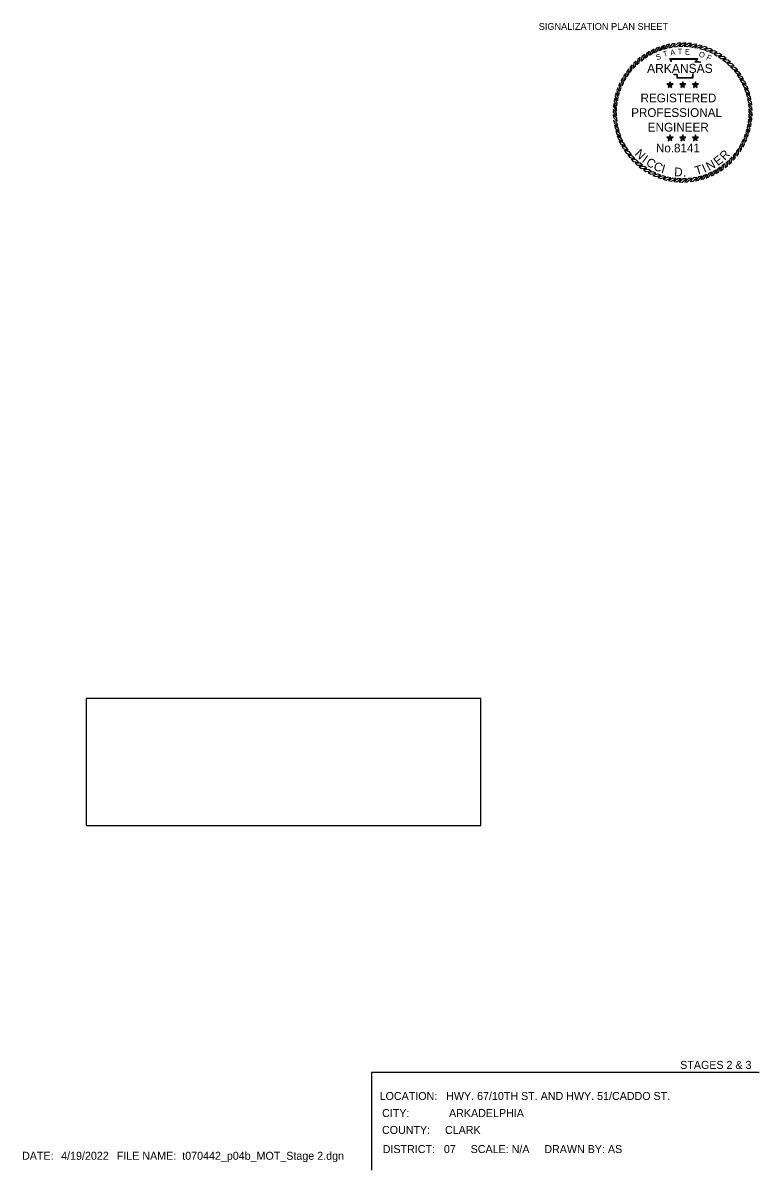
# Model space of a CAD drawing. Extents: x 418532 to 419834, y -565899 to -565282.
# Drawn here: x 419448 to 419834, y -565899 to -565297 of the extents above; entities that cross this region are included whole.
import ezdxf

# ---------------------------------------------------------------- set-up
doc = ezdxf.new("R2010")
doc.units = 0
for name, color, linetype in [('G-ANNO-SYMB', 7, 'Continuous'), ('G-ANNO-TEXT', 7, 'Continuous'), ('Level 10', 7, 'Continuous'), ('Level 57', 7, 'Continuous'), ('V-SIGNAL-LOOP', 7, 'Continuous')]:
    doc.layers.add(name, color=color, linetype=linetype)

msp = doc.modelspace()

# ---------------------------------------------------------------- linework, layer by layer
at = {"layer": 'G-ANNO-SYMB'}
for points in [[(419790.16, -565307.34), (419788.61, -565307.54), (419786.7, -565309.59), (419788.37, -565309.27)], [(419793.02, -565307.15), (419791.46, -565307.23), (419789.39, -565309.11), (419791.08, -565308.93)], [(419795.89, -565307.18), (419794.32, -565307.13), (419792.12, -565308.85), (419793.81, -565308.8)], [(419798.74, -565307.43), (419797.18, -565307.26), (419794.85, -565308.81), (419796.54, -565308.89)], [(419774.13, -565313.06), (419772.83, -565313.95), (419772.06, -565316.64), (419773.4, -565315.6)], [(419776.58, -565311.59), (419775.22, -565312.37), (419774.24, -565314.99), (419775.66, -565314.06)], [(419779.15, -565310.32), (419777.73, -565310.99), (419776.55, -565313.53), (419778.04, -565312.71)], [(419781.81, -565309.25), (419780.34, -565309.81), (419778.96, -565312.25), (419780.51, -565311.55)], [(419784.54, -565308.4), (419783.03, -565308.84), (419781.47, -565311.16), (419783.07, -565310.58)], [(419787.33, -565307.76), (419785.8, -565308.08), (419784.06, -565310.27), (419785.69, -565309.82)], [(419801.56, -565307.91), (419800.02, -565307.62), (419797.58, -565308.98), (419799.26, -565309.19)], [(419804.34, -565308.61), (419802.83, -565308.2), (419800.28, -565309.36), (419801.94, -565309.7)], [(419807.05, -565309.52), (419805.58, -565309), (419802.95, -565309.95), (419804.58, -565310.42)], [(419809.69, -565310.65), (419808.26, -565310.01), (419805.56, -565310.75), (419807.15, -565311.35)], [(419812.23, -565311.97), (419810.85, -565311.22), (419808.11, -565311.76), (419809.64, -565312.48)], [(419814.65, -565313.5), (419813.34, -565312.64), (419810.56, -565312.96), (419812.03, -565313.8)], [(419767.55, -565318.56), (419766.49, -565319.73), (419766.37, -565322.52), (419767.43, -565321.2)], [(419769.59, -565316.56), (419768.45, -565317.64), (419768.11, -565320.41), (419769.27, -565319.18)], [(419771.79, -565314.72), (419770.57, -565315.71), (419770.01, -565318.45), (419771.27, -565317.31)], [(419816.95, -565315.21), (419815.71, -565314.25), (419812.92, -565314.35), (419814.32, -565315.3)], [(419819.11, -565317.09), (419817.95, -565316.04), (419815.15, -565315.91), (419816.48, -565316.97)], [(419821.11, -565319.14), (419820.04, -565317.99), (419817.26, -565317.65), (419818.5, -565318.81)], [(419822.95, -565321.33), (419821.96, -565320.11), (419819.23, -565319.55), (419820.37, -565320.81)], [(419762.43, -565325.45), (419761.68, -565326.82), (419762.21, -565329.57), (419762.94, -565328.03)], [(419763.96, -565323.02), (419763.1, -565324.33), (419763.41, -565327.11), (419764.25, -565325.64)], [(419765.66, -565320.72), (419764.71, -565321.96), (419764.8, -565324.76), (419765.76, -565323.35)], [(419824.61, -565323.67), (419823.72, -565322.37), (419821.03, -565321.6), (419822.07, -565322.94)], [(419826.08, -565326.13), (419825.3, -565324.77), (419822.68, -565323.79), (419823.61, -565325.2)], [(419759.98, -565330.62), (419759.45, -565332.09), (419760.41, -565334.72), (419760.88, -565333.09)], [(419761.11, -565327.98), (419760.46, -565329.41), (419761.21, -565332.11), (419761.81, -565330.52)], [(419787.4, -565329.08), (419787.02, -565328.57), (419785.81, -565328.57), (419786.79, -565329.28)], [(419787.4, -565329.08), (419786.79, -565329.28), (419786.42, -565330.43), (419787.4, -565329.72)], [(419787.4, -565329.08), (419787.77, -565328.57), (419787.4, -565327.41), (419787.02, -565328.57)], [(419787.4, -565329.08), (419788, -565329.28), (419788.98, -565328.57), (419787.77, -565328.57)], [(419787.4, -565329.08), (419787.4, -565329.72), (419788.38, -565330.43), (419788, -565329.28)], [(419794.06, -565329.08), (419793.69, -565328.57), (419792.48, -565328.57), (419793.46, -565329.28)], [(419794.06, -565329.08), (419793.46, -565329.28), (419793.08, -565330.43), (419794.06, -565329.72)], [(419794.06, -565329.08), (419794.44, -565328.57), (419794.06, -565327.41), (419793.69, -565328.57)], [(419794.06, -565329.08), (419794.67, -565329.28), (419795.65, -565328.57), (419794.44, -565328.57)], [(419794.06, -565329.08), (419794.06, -565329.72), (419795.04, -565330.43), (419794.67, -565329.28)], [(419800.73, -565329.08), (419800.36, -565328.57), (419799.15, -565328.57), (419800.13, -565329.28)], [(419800.73, -565329.08), (419800.13, -565329.28), (419799.75, -565330.43), (419800.73, -565329.72)], [(419800.73, -565329.08), (419801.11, -565328.57), (419800.73, -565327.41), (419800.36, -565328.57)], [(419800.73, -565329.08), (419801.34, -565329.28), (419802.32, -565328.57), (419801.11, -565328.57)], [(419800.73, -565329.08), (419800.73, -565329.72), (419801.71, -565330.43), (419801.34, -565329.28)], [(419827.35, -565328.69), (419826.68, -565327.27), (419824.15, -565326.09), (419824.96, -565327.58)], [(419828.42, -565331.35), (419827.86, -565329.88), (419825.43, -565328.51), (419826.12, -565330.05)], [(419829.27, -565334.08), (419828.83, -565332.58), (419826.51, -565331.01), (419827.09, -565332.61)], [(419758.37, -565336.11), (419758.08, -565337.65), (419759.43, -565340.1), (419759.65, -565338.41)], [(419759.07, -565333.33), (419758.66, -565334.85), (419759.82, -565337.39), (419760.16, -565335.73)], [(419829.91, -565336.87), (419829.59, -565335.34), (419827.4, -565333.6), (419827.85, -565335.23)], [(419830.33, -565339.71), (419830.13, -565338.15), (419828.09, -565336.24), (419828.4, -565337.91)], [(419757.64, -565341.79), (419757.59, -565343.35), (419759.31, -565345.56), (419759.26, -565343.86)], [(419757.89, -565338.93), (419757.72, -565340.49), (419759.27, -565342.82), (419759.35, -565341.13)], [(419830.53, -565342.56), (419830.45, -565341), (419828.56, -565338.94), (419828.74, -565340.62)], [(419830.49, -565345.43), (419830.54, -565343.86), (419828.82, -565341.66), (419828.87, -565343.35)], [(419757.6, -565344.65), (419757.68, -565346.22), (419759.57, -565348.28), (419759.39, -565346.59)], [(419757.8, -565347.51), (419758, -565349.06), (419760.04, -565350.97), (419759.73, -565349.3)], [(419829.76, -565351.1), (419830.05, -565349.56), (419828.7, -565347.12), (419828.48, -565348.8)], [(419830.24, -565348.28), (419830.41, -565346.72), (419828.86, -565344.39), (419828.78, -565346.08)], [(419758.22, -565350.34), (419758.54, -565351.88), (419760.73, -565353.62), (419760.28, -565351.98)], [(419758.86, -565353.13), (419759.3, -565354.64), (419761.62, -565356.2), (419761.04, -565354.61)], [(419787.4, -565357.01), (419787.77, -565356.5), (419787.4, -565355.34), (419787.02, -565356.5)], [(419794.06, -565357.01), (419794.44, -565356.5), (419794.06, -565355.34), (419793.69, -565356.5)], [(419800.73, -565357.01), (419801.11, -565356.5), (419800.73, -565355.34), (419800.36, -565356.5)], [(419827.02, -565359.23), (419827.67, -565357.8), (419826.92, -565355.11), (419826.32, -565356.69)], [(419828.15, -565356.6), (419828.68, -565355.12), (419827.72, -565352.49), (419827.25, -565354.12)], [(419829.06, -565353.88), (419829.47, -565352.37), (419828.31, -565349.82), (419827.97, -565351.48)], [(419759.71, -565355.87), (419760.27, -565357.33), (419762.7, -565358.71), (419762.01, -565357.16)], [(419760.78, -565358.52), (419761.45, -565359.94), (419763.98, -565361.12), (419763.17, -565359.64)], [(419762.05, -565361.09), (419762.83, -565362.45), (419765.45, -565363.43), (419764.52, -565362.01)], [(419787.4, -565357.01), (419787.02, -565356.5), (419785.81, -565356.5), (419786.79, -565357.21)], [(419787.4, -565357.01), (419786.79, -565357.21), (419786.42, -565358.36), (419787.4, -565357.65)], [(419787.4, -565357.01), (419788, -565357.21), (419788.98, -565356.5), (419787.77, -565356.5)], [(419787.4, -565357.01), (419787.4, -565357.65), (419788.38, -565358.36), (419788, -565357.21)], [(419794.06, -565357.01), (419793.69, -565356.5), (419792.48, -565356.5), (419793.46, -565357.21)], [(419794.06, -565357.01), (419793.46, -565357.21), (419793.08, -565358.36), (419794.06, -565357.65)], [(419794.06, -565357.01), (419794.67, -565357.21), (419795.65, -565356.5), (419794.44, -565356.5)], [(419794.06, -565357.01), (419794.06, -565357.65), (419795.04, -565358.36), (419794.67, -565357.21)], [(419800.73, -565357.01), (419800.36, -565356.5), (419799.15, -565356.5), (419800.13, -565357.21)], [(419800.73, -565357.01), (419800.13, -565357.21), (419799.75, -565358.36), (419800.73, -565357.65)], [(419800.73, -565357.01), (419801.34, -565357.21), (419802.32, -565356.5), (419801.11, -565356.5)], [(419800.73, -565357.01), (419800.73, -565357.65), (419801.71, -565358.36), (419801.34, -565357.21)], [(419824.17, -565364.19), (419825.03, -565362.88), (419824.72, -565360.1), (419823.88, -565361.58)], [(419825.7, -565361.77), (419826.45, -565360.39), (419825.92, -565357.65), (419825.19, -565359.18)], [(419763.52, -565363.55), (419764.41, -565364.84), (419767.09, -565365.61), (419766.06, -565364.27)], [(419765.18, -565365.88), (419766.16, -565367.1), (419768.9, -565367.66), (419767.76, -565366.41)], [(419818.54, -565370.65), (419819.68, -565369.58), (419820.02, -565366.8), (419818.86, -565368.04)], [(419820.58, -565368.65), (419821.64, -565367.49), (419821.76, -565364.69), (419820.7, -565366.02)], [(419822.47, -565366.49), (419823.42, -565365.25), (419823.33, -565362.46), (419822.37, -565363.86)], [(419767.02, -565368.08), (419768.09, -565369.22), (419770.87, -565369.56), (419769.63, -565368.4)], [(419769.02, -565370.13), (419770.18, -565371.18), (419772.98, -565371.3), (419771.65, -565370.24)], [(419771.18, -565372.01), (419772.42, -565372.97), (419775.21, -565372.87), (419773.81, -565371.92)], [(419773.48, -565373.72), (419774.79, -565374.57), (419777.57, -565374.26), (419776.1, -565373.42)], [(419808.98, -565376.89), (419810.4, -565376.22), (419811.58, -565373.69), (419810.09, -565374.5)], [(419811.55, -565375.62), (419812.91, -565374.84), (419813.89, -565372.22), (419812.47, -565373.15)], [(419814, -565374.15), (419815.3, -565373.26), (419816.07, -565370.58), (419814.73, -565371.62)], [(419816.34, -565372.49), (419817.56, -565371.51), (419818.12, -565368.77), (419816.86, -565369.91)], [(419775.9, -565375.24), (419777.28, -565375.99), (419780.02, -565375.46), (419778.49, -565374.74)], [(419778.44, -565376.57), (419779.87, -565377.21), (419782.57, -565376.46), (419780.98, -565375.86)], [(419781.08, -565377.69), (419782.55, -565378.22), (419785.18, -565377.26), (419783.55, -565376.79)], [(419783.79, -565378.6), (419785.3, -565379.01), (419787.85, -565377.85), (419786.19, -565377.51)], [(419786.57, -565379.3), (419788.11, -565379.59), (419790.55, -565378.24), (419788.87, -565378.03)], [(419789.39, -565379.78), (419790.95, -565379.95), (419793.28, -565378.41), (419791.59, -565378.33)], [(419792.24, -565380.04), (419793.81, -565380.08), (419796.01, -565378.36), (419794.32, -565378.41)], [(419795.11, -565380.07), (419796.67, -565379.99), (419798.74, -565378.1), (419797.05, -565378.29)], [(419797.96, -565379.87), (419799.52, -565379.67), (419801.43, -565377.63), (419799.76, -565377.95)], [(419800.8, -565379.46), (419802.33, -565379.13), (419804.07, -565376.94), (419802.44, -565377.39)], [(419803.59, -565378.82), (419805.1, -565378.37), (419806.66, -565376.06), (419805.06, -565376.63)], [(419806.32, -565377.96), (419807.79, -565377.4), (419809.17, -565374.97), (419807.62, -565375.67)]]:
    msp.add_lwpolyline(points, close=True, dxfattribs=at)
for points in [[(419788.22, -565317.13), (419787.37, -565315.29), (419802.08, -565315.28), (419800.85, -565316.83), (419801.85, -565316.82), (419802.69, -565316.8), (419803.52, -565316.9)], [(419788.43, -565317.04), (419787.74, -565315.53), (419801.6, -565315.52), (419800.37, -565317.07), (419801.86, -565317.05), (419802.68, -565317.04), (419803.5, -565317.13)], [(419799.76, -565323.3), (419799.51, -565323.5), (419799.43, -565323.81), (419799.35, -565324.57), (419799.35, -565325.59), (419791.13, -565325.59), (419791.13, -565324.22), (419791.13, -565323.91), (419790.8, -565323.81), (419789.63, -565323.81), (419789.43, -565323.49)], [(419799.62, -565323.12), (419799.31, -565323.37), (419799.2, -565323.76), (419799.11, -565324.56), (419799.11, -565325.36), (419791.37, -565325.36), (419791.37, -565324.22), (419791.37, -565323.74), (419790.84, -565323.58), (419789.76, -565323.58), (419789.62, -565323.36)]]:
    msp.add_lwpolyline(points, dxfattribs=at)
at = {"layer": 'Level 57'}
for points in [[(419630.59, -565847.55), (419630.59, -565898.75)], [(419834.17, -565847.55), (419630.59, -565847.55)]]:
    msp.add_lwpolyline(points, dxfattribs=at)
at = {"layer": 'V-SIGNAL-LOOP'}
msp.add_lwpolyline([(419480.77, -565717.89), (419688.06, -565717.89), (419688.06, -565651.22), (419480.77, -565651.22)], close=True, dxfattribs=at)

# ---------------------------------------------------------------- texts
at = {"layer": 'G-ANNO-SYMB'}
for s, height, rotation, p in [('S', 2.9, 19.77256, (419780.56, -565316.17)), ('T', 2.9, 16.90148, (419784.25, -565314.51)), ('A', 2.9, 8.67877, (419787.77, -565313.59)), ('T', 2.9, 1.47887, (419791.52, -565313.01)), ('E', 2.9, 356.67203, (419795.23, -565313.1)), ('O', 2.9, 341.2218, (419802.28, -565314.1)), ('F', 2.9, 335.36282, (419806.19, -565315.63)), ('N', 4.59, 315.26758, (419768.58, -565365.6)), ('I', 4.59, 324.21406, (419772.31, -565369.3)), ('C', 4.59, 328.68731, (419774.38, -565370.92)), ('E', 4.59, 37.64979, (419812.49, -565371.78)), ('R', 4.59, 45.47796, (419816.16, -565369.01)), ('C', 4.59, 336.51548, (419778.29, -565373.34)), ('I', 4.59, 344.34365, (419782.48, -565375.22)), ('D', 4.59, 356.64507, (419789.49, -565376.96)), ('T', 4.59, 16.77466, (419801.24, -565376.5)), ('I', 4.59, 24.23006, (419805.45, -565375.29)), ('N', 4.59, 28.7033, (419807.89, -565374.3)), ('.', 4.59, 4.84601, (419794.29, -565377.27))]:
    msp.add_text(s, height=height, rotation=rotation, dxfattribs=at).set_placement(p)
for s, height, p in [('ARKANSAS', 4.737, (419775.34, -565322.77)), ('REGISTERED', 4.585, (419771.9, -565338.23)), ('PROFESSIONAL', 4.5855, (419766.99, -565345.9)), ('ENGINEER', 4.585, (419775.72, -565353.57)), ('No.8141', 4.567, (419780, -565364.5))]:
    msp.add_text(s, height=height, dxfattribs=at).set_placement(p)
at = {"layer": 'G-ANNO-TEXT'}
msp.add_text('SIGNALIZATION PLAN SHEET', height=3.6, dxfattribs=at).set_placement((419718.44, -565300.21))
at = {"layer": 'Level 10'}
for s, p in [('STAGES 2 & 3', (419792.74, -565845.65)), ('LOCATION:   HWY. 67/10TH ST. AND HWY. 51/CADDO ST.', (419634.9, -565861.97)), ('CITY:', (419636.19, -565870.93)), (' ARKADELPHIA', (419669.79, -565870.93)), ('COUNTY:     CLARK', (419636.14, -565879.8)), ('DISTRICT:   07     SCALE: N/A     DRAWN BY: AS', (419636.51, -565889.83)), ('DATE:  ', (419447.09, -565893.35)), ('4/19/2022', (419467.63, -565893.35)), ('  FILE NAME: ', (419493.72, -565893.35)), ('t070442_p04b_MOT_Stage 2.dgn', (419531.22, -565893.35))]:
    msp.add_text(s, height=4.2, rotation=360, dxfattribs=at).set_placement(p)

doc.saveas('drawing.dxf')
